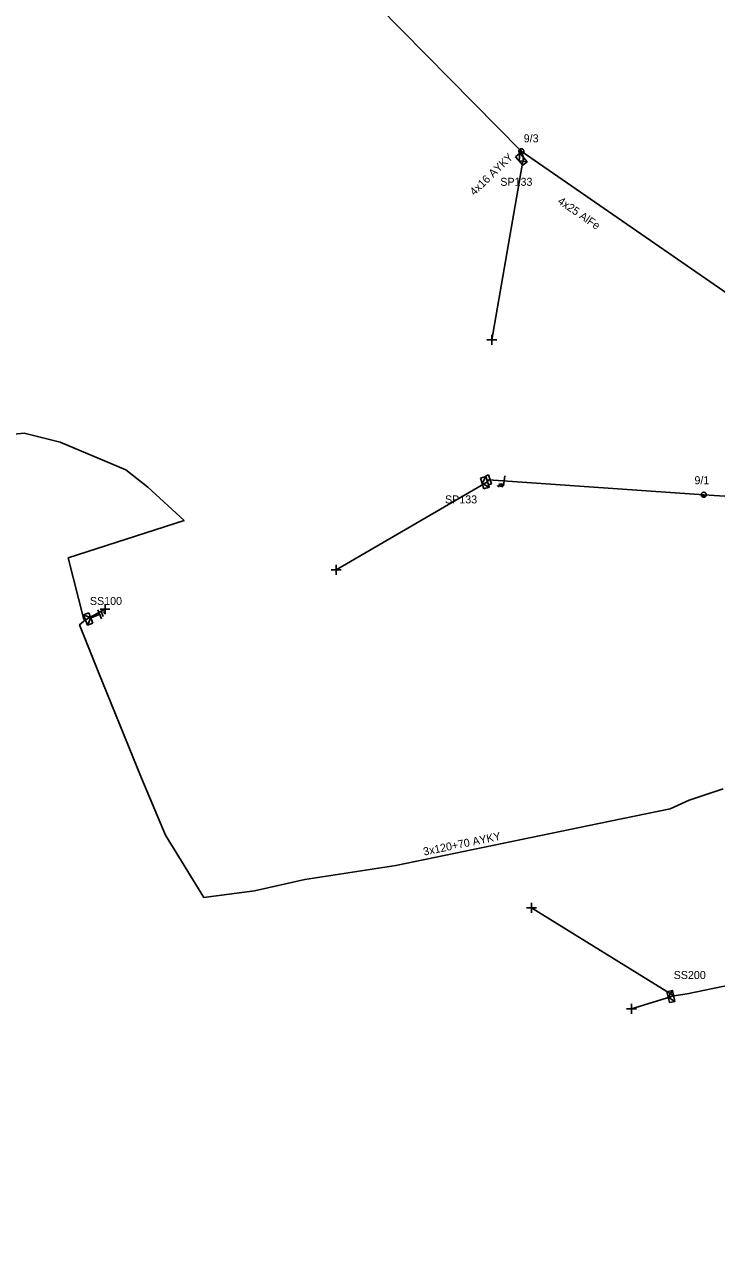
# Model space of a CAD drawing. Extents: x -717562 to -713845, y -1151196 to -1143903.
# Drawn here: x -717256.5 to -717170, y -1144446.2 to -1144293.2 of the extents above; entities that cross this region are included whole.
import ezdxf

# ---------------------------------------------------------------- set-up
doc = ezdxf.new("R2010")
doc.units = 0
for name, color, linetype in [('Vrstva 1', 7, 'Continuous'), ('Vrstva 12', 7, 'Continuous'), ('Vrstva 13', 7, 'Continuous'), ('Vrstva 14', 7, 'Continuous'), ('Vrstva 15', 7, 'Continuous'), ('Vrstva 18', 7, 'Continuous'), ('Vrstva 2', 7, 'Continuous'), ('Vrstva 31', 7, 'Continuous'), ('Vrstva 33', 7, 'Continuous'), ('Vrstva 34', 7, 'Continuous'), ('Vrstva 4', 7, 'Continuous'), ('Vrstva 52', 7, 'Continuous'), ('Vrstva 54', 7, 'Continuous'), ('Vrstva 59', 7, 'Continuous'), ('Vrstva 9', 7, 'Continuous')]:
    doc.layers.add(name, color=color, linetype=linetype)

# ---------------------------------------------------------------- blocks, each defined once
blk = doc.blocks.new('NN440')
at = {"layer": 'Vrstva 2'}
for points in [[(0.63, 0), (0.63, 0.06), (0.62, 0.13), (0.6, 0.19), (0.58, 0.25), (0.55, 0.31), (0.51, 0.37), (0.47, 0.42), (0.42, 0.46), (0.37, 0.51), (0.32, 0.54), (0.26, 0.57), (0.2, 0.59), (0.13, 0.61), (0.07, 0.62), (0, 0.63), (-0.06, 0.62), (-0.13, 0.61), (-0.19, 0.59), (-0.26, 0.57), (-0.31, 0.54), (-0.37, 0.51), (-0.42, 0.46), (-0.47, 0.42), (-0.51, 0.37), (-0.54, 0.31), (-0.57, 0.25), (-0.6, 0.19), (-0.62, 0.13), (-0.63, 0.06), (-0.63, 0), (-0.63, -0.07), (-0.62, -0.14), (-0.6, -0.2), (-0.57, -0.26), (-0.54, -0.32), (-0.51, -0.37), (-0.47, -0.43), (-0.42, -0.47), (-0.37, -0.51), (-0.31, -0.55), (-0.26, -0.58), (-0.19, -0.6), (-0.13, -0.62), (-0.06, -0.63), (0, -0.63), (0.07, -0.63), (0.13, -0.62), (0.2, -0.6), (0.26, -0.58), (0.32, -0.55), (0.37, -0.51), (0.42, -0.47), (0.47, -0.43), (0.51, -0.37), (0.55, -0.32), (0.58, -0.26), (0.6, -0.2), (0.62, -0.14), (0.63, -0.07), (0.63, 0)], [(-0.63, 0), (0.63, 0)], [(-0.6, -0.18), (0.57, -0.18)], [(-0.51, -0.32), (0.5, -0.32)], [(-0.37, -0.47), (0.35, -0.47)]]:
    blk.add_lwpolyline(points, dxfattribs=at)
blk = doc.blocks.new('NN840')
at = {"layer": 'Vrstva 15'}
for points in [[(0, 0.62), (0, -0.63)], [(-0.75, -0.71), (-0.75, -0.66)], [(-0.73, -0.76), (-0.75, -0.71)], [(-0.66, -0.8), (-0.73, -0.76)], [(-0.63, -0.8), (-0.66, -0.8)], [(-0.56, -0.76), (-0.63, -0.8)], [(-0.54, -0.71), (-0.56, -0.76)], [(-0.54, -0.38), (-0.54, -0.71)], [(-0.33, -0.38), (-0.33, -0.8)], [(-0.33, -0.64), (-0.13, -0.38)], [(-0.26, -0.56), (-0.09, -0.8)]]:
    blk.add_lwpolyline(points, dxfattribs=at)
blk = doc.blocks.new('NN800')
at = {"layer": 'Vrstva 1'}
for points in [[(-0.44, 0.44), (0.44, -0.44)], [(-0.44, -0.44), (0.44, 0.44)]]:
    blk.add_lwpolyline(points, dxfattribs=at)
blk = doc.blocks.new('NN630')
at = {"layer": 'Vrstva 9'}
for points in [[(0, -0.7), (-0.7, 0)], [(-0.7, -0.7), (-0.7, 0), (0.7, 0), (0.7, -0.7)], [(-0.7, -0.7), (0.7, -0.7)], [(0, -0.7), (0.7, 0)]]:
    blk.add_lwpolyline(points, dxfattribs=at)
blk = doc.blocks.new('NN810')
at = {"layer": 'Vrstva 14'}
for points in [[(0, -0.64), (0, -1.89)], [(0.63, -1.89), (-0.62, -1.89)], [(0.39, -2.2), (-0.4, -2.2)], [(0, -2.52), (-0.12, -2.52)], [(0.14, -2.52), (0, -2.52)]]:
    blk.add_lwpolyline(points, dxfattribs=at)
blk = doc.blocks.new('NN515')
at = {"layer": 'Vrstva 2'}
for points in [[(-0.59, 0.18), (0.59, 0.18)], [(-0.59, 0.18), (-0.59, -0.18)], [(0.59, 0.18), (0.59, -0.18)]]:
    blk.add_lwpolyline(points, dxfattribs=at)

msp = doc.modelspace()

# ---------------------------------------------------------------- linework, layer by layer
at = {"layer": 'Vrstva 1'}
msp.add_lwpolyline([(-717142.08, -1144353.91), (-717164.45, -1144329.75), (-717194.36, -1144309.08), (-717215.26, -1144287.87), (-717232.51, -1144259.72)], dxfattribs=at)
at = {"layer": 'Vrstva 4'}
msp.add_lwpolyline([(-717142.08, -1144353.91), (-717171.55, -1144352.01), (-717198.45, -1144350.14), (-717198.58, -1144350.41)], dxfattribs=at)
at = {"layer": 'Vrstva 52'}
for points in [[(-717194.36, -1144309.08), (-717194.08, -1144309.85)], [(-717558.12, -1144385.29), (-717557.8, -1144386.03), (-717547.29, -1144381.97), (-717545.44, -1144381.16), (-717530.76, -1144374.75), (-717512.69, -1144368.91), (-717480.96, -1144362.24), (-717441.02, -1144360.89), (-717408.07, -1144358.07), (-717348.37, -1144352.48), (-717323.36, -1144350.16), (-717284.48, -1144346.98), (-717256.52, -1144344.3), (-717252.03, -1144345.42), (-717243.81, -1144348.89), (-717241.04, -1144351.07), (-717236.52, -1144355.21), (-717251.01, -1144359.9), (-717249.05, -1144367.58), (-717248.84, -1144367.65)], [(-717169.11, -1144388.76), (-717173.38, -1144390.19), (-717175.75, -1144391.27), (-717184.65, -1144393.09), (-717210.04, -1144398.34), (-717221.42, -1144400.07), (-717227.72, -1144401.52), (-717234.07, -1144402.33), (-717238.86, -1144394.54), (-717241.86, -1144387.44), (-717247.27, -1144374.1), (-717249.58, -1144368.26), (-717248.84, -1144367.65)], [(-717096.28, -1144453.2), (-717101.37, -1144445.81), (-717105.87, -1144436.81), (-717109.56, -1144430.47), (-717110.66, -1144430), (-717112.18, -1144428.74), (-717113.51, -1144427.1), (-717120.51, -1144414.15), (-717124.1, -1144405.71), (-717124.9, -1144403.48), (-717125.63, -1144402.56), (-717126.37, -1144402.42), (-717127.33, -1144402.48), (-717133.04, -1144403.33), (-717146.3, -1144407.03), (-717157.06, -1144410.27), (-717165.06, -1144412.77), (-717169.2, -1144413.46), (-717173.63, -1144414.38), (-717175.31, -1144414.63)]]:
    msp.add_lwpolyline(points, dxfattribs=at)
at = {"layer": 'Vrstva 59'}
for points in [[(-717194.08, -1144309.85), (-717198.06, -1144332.63)], [(-717198.58, -1144350.41), (-717217.5, -1144361.38)], [(-717248.84, -1144367.65), (-717246.41, -1144366.32)], [(-717175.31, -1144414.63), (-717193.08, -1144403.61)], [(-717175.31, -1144414.63), (-717180.58, -1144416.24)]]:
    msp.add_lwpolyline(points, dxfattribs=at)

# ---------------------------------------------------------------- block references
at = {"layer": 'Vrstva 13', "yscale": 0.5}
for p, xscale, rotation in [((-717194.36, -1144309.08), 0.5, -50.36526938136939), ((-717171.55, -1144352.01), 0.49999999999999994, -6.729789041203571)]:
    msp.add_blockref('NN440', p, dxfattribs=dict(at, xscale=xscale, rotation=rotation))
at = {"layer": 'Vrstva 13', "rotation": -73.2801260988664}
msp.add_blockref('NN515', (-717198.45, -1144350.14), dxfattribs=at)
at = {"layer": 'Vrstva 15', "rotation": 111.58117222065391}
msp.add_blockref('NN810', (-717248.84, -1144367.65), dxfattribs=at)
at = {"layer": 'Vrstva 18', "rotation": -6.729788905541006}
msp.add_blockref('NN840', (-717196.5, -1144350.27), dxfattribs=at)
at = {"layer": 'Vrstva 31'}
for p, rotation in [((-717194.08, -1144309.85), -49.92435552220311), ((-717198.58, -1144350.41), -72.75818514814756), ((-717248.84, -1144367.65), 111.58117215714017), ((-717175.31, -1144414.63), -76.77811111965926)]:
    msp.add_blockref('NN630', p, dxfattribs=dict(at, rotation=rotation))
at = {"layer": 'Vrstva 34', "rotation": 45}
for p in [(-717198.06, -1144332.63), (-717217.5, -1144361.38), (-717246.41, -1144366.32), (-717193.08, -1144403.61), (-717180.58, -1144416.24)]:
    msp.add_blockref('NN800', p, dxfattribs=at)

# ---------------------------------------------------------------- texts
at = {"layer": 'Vrstva 12'}
for s, p in [('9/3', (-717194.06, -1144307.97)), ('9/1', (-717172.71, -1144350.69))]:
    msp.add_text(s, height=1, dxfattribs=at).set_placement(p)
at = {"layer": 'Vrstva 2'}
msp.add_text('4x25 AlFe', height=1, rotation=325.471, dxfattribs=at).set_placement((-717189.9, -1144315.53))
at = {"layer": 'Vrstva 33'}
for s, p in [('SP133', (-717196.99, -1144313.4)), ('SP133', (-717203.9, -1144353.09)), ('SS100', (-717248.3, -1144365.78)), ('SS200', (-717175.31, -1144412.52))]:
    msp.add_text(s, height=1, dxfattribs=at).set_placement(p)
at = {"layer": 'Vrstva 54'}
for s, rotation, p in [('4x16 AYKY', 43.967, (-717200.23, -1144314.69)), ('3x120+70 AYKY', 11.683, (-717206.51, -1144397.11))]:
    msp.add_text(s, height=1, rotation=rotation, dxfattribs=at).set_placement(p)

doc.saveas('drawing.dxf')
